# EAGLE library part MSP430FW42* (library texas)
MIXED SIGNAL MICROCONTROLLER created with make-symbol-device-package-bsdl - text option Source: www.ti.com .. MSP430 Microcontroller.pdf
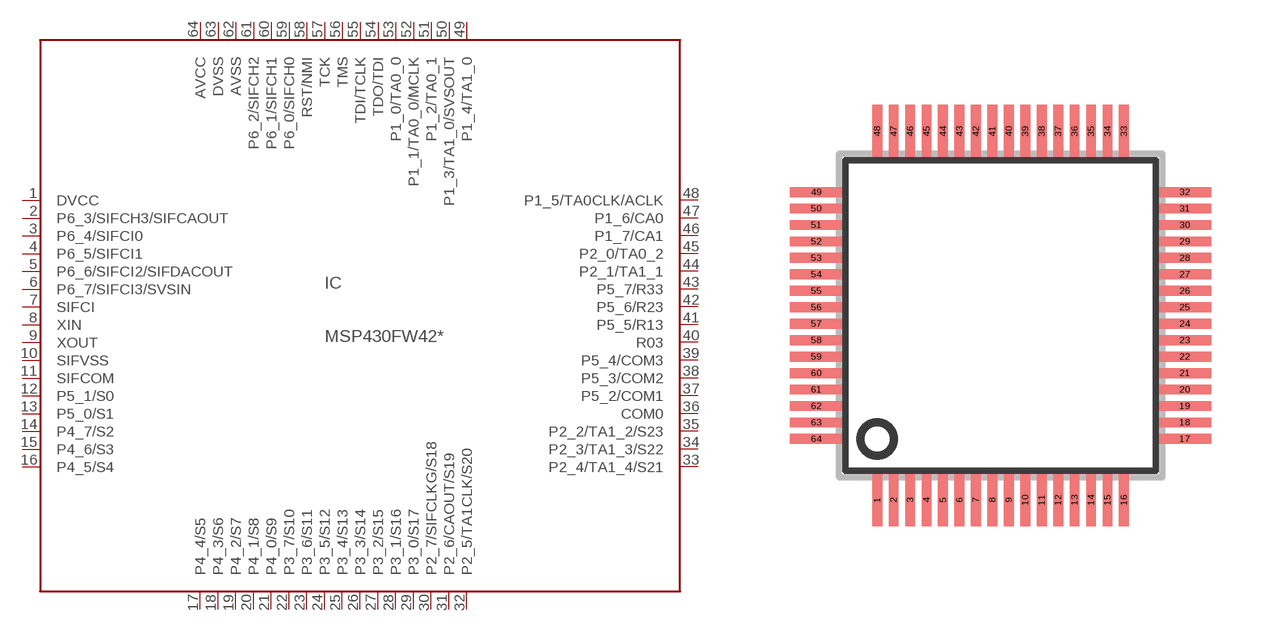
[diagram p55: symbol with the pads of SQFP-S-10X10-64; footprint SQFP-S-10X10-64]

Designator prefix IC

## MSP430FW42IP (OC_FARNELL: unknown; OC_NEWARK: unknown)  [SQFP-S-10X10-64]
1  DVCC  pwr
2  P6_3/SIFCH3/SIFCAOUT
3  P6_4/SIFCI0
4  P6_5/SIFCI1
5  P6_6/SIFCI2/SIFDACOUT
6  P6_7/SIFCI3/SVSIN
7  SIFCI  in
8  XIN  in
9  XOUT  out
10  SIFVSS  pas
11  SIFCOM  out
12  P5_1/S0
13  P5_0/S1
14  P4_7/S2
15  P4_6/S3
16  P4_5/S4
17  P4_4/S5
18  P4_3/S6
19  P4_2/S7
20  P4_1/S8
21  P4_0/S9
22  P3_7/S10
23  P3_6/S11
24  P3_5/S12
25  P3_4/S13
26  P3_3/S14
27  P3_2/S15
28  P3_1/S16
29  P3_0/S17
30  P2_7/SIFCLKG/S18
31  P2_6/CAOUT/S19
32  P2_5/TA1CLK/S20
33  P2_4/TA1_4/S21
34  P2_3/TA1_3/S22
35  P2_2/TA1_2/S23
36  COM0  out
37  P5_2/COM1
38  P5_3/COM2
39  P5_4/COM3
40  R03  in
41  P5_5/R13
42  P5_6/R23
43  P5_7/R33
44  P2_1/TA1_1
45  P2_0/TA0_2
46  P1_7/CA1
47  P1_6/CA0
48  P1_5/TA0CLK/ACLK
49  P1_4/TA1_0
50  P1_3/TA1_0/SVSOUT
51  P1_2/TA0_1
52  P1_1/TA0_0/MCLK
53  P1_0/TA0_0
54  TDO/TDI
55  TDI/TCLK  in
56  TMS  in
57  TCK  in
58  RST/NMI  in
59  P6_0/SIFCH0
60  P6_1/SIFCH1
61  P6_2/SIFCH2
62  AVSS  pwr
63  DVSS  pwr
64  AVCC  pwr

## Footprint SQFP-S-10X10-64 (pad centres in mm)
QFP64 shrink quad flat pack, square
smd 0.3 x 1.6: 1 -3.75,-5.6; 2 -3.25,-5.6; 3 -2.75,-5.6; 4 -2.25,-5.6; 5 -1.75,-5.6; 6 -1.25,-5.6; 7 -0.75,-5.6; 8 -0.25,-5.6; 9 0.25,-5.6; 10 0.75,-5.6; 11 1.25,-5.6; 12 1.75,-5.6; 13 2.25,-5.6; 14 2.75,-5.6; 15 3.25,-5.6; 16 3.75,-5.6; 33 3.75,5.6; 34 3.25,5.6; 35 2.75,5.6; 36 2.25,5.6; 37 1.75,5.6; 38 1.25,5.6; 39 0.75,5.6; 40 0.25,5.6; 41 -0.25,5.6; 42 -0.75,5.6; 43 -1.25,5.6; 44 -1.75,5.6; 45 -2.25,5.6; 46 -2.75,5.6; 47 -3.25,5.6; 48 -3.75,5.6
smd 1.6 x 0.3: 17 5.6,-3.75; 18 5.6,-3.25; 19 5.6,-2.75; 20 5.6,-2.25; 21 5.6,-1.75; 22 5.6,-1.25; 23 5.6,-0.75; 24 5.6,-0.25; 25 5.6,0.25; 26 5.6,0.75; 27 5.6,1.25; 28 5.6,1.75; 29 5.6,2.25; 30 5.6,2.75; 31 5.6,3.25; 32 5.6,3.75; 49 -5.6,3.75; 50 -5.6,3.25; 51 -5.6,2.75; 52 -5.6,2.25; 53 -5.6,1.75; 54 -5.6,1.25; 55 -5.6,0.75; 56 -5.6,0.25; 57 -5.6,-0.25; 58 -5.6,-0.75; 59 -5.6,-1.25; 60 -5.6,-1.75; 61 -5.6,-2.25; 62 -5.6,-2.75; 63 -5.6,-3.25; 64 -5.6,-3.75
